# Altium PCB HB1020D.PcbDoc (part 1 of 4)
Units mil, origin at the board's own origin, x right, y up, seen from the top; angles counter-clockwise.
Board outline 4729.44 x 3075.9 mil, 2 copper layers (Top Layer, Bottom Layer); 113 components, 129 nets, 454 pads, 503 vias.
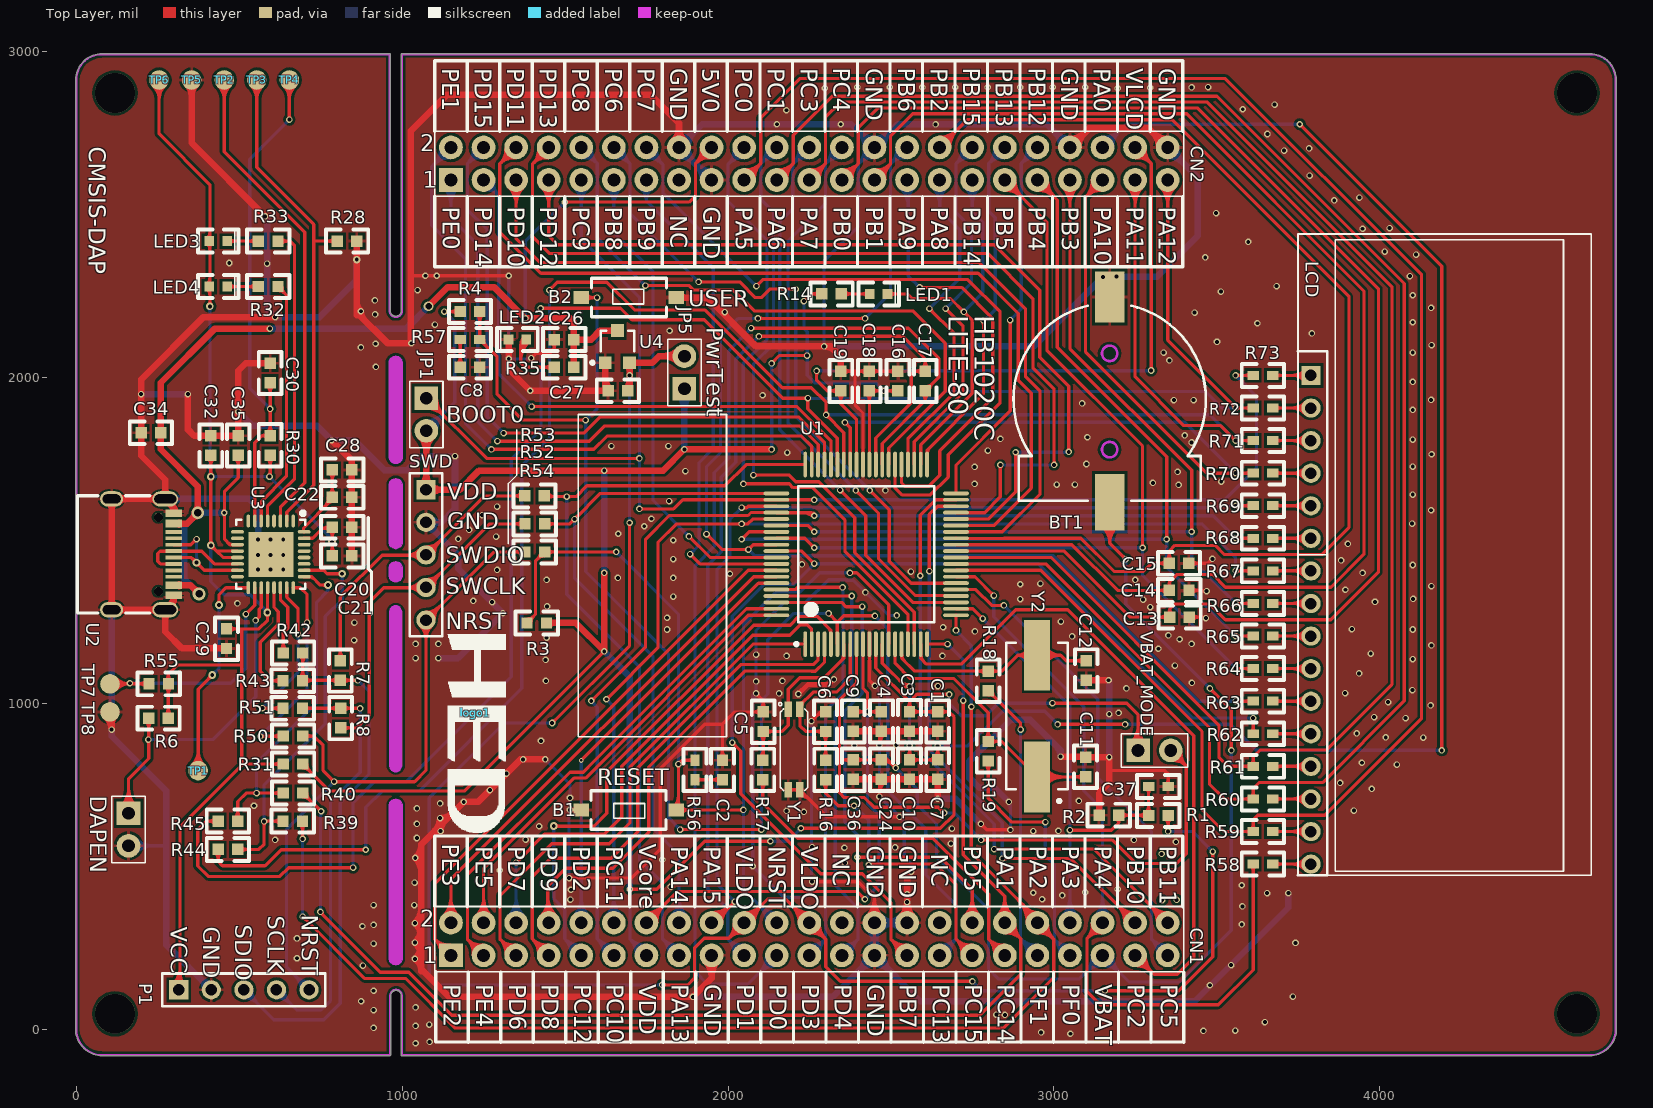
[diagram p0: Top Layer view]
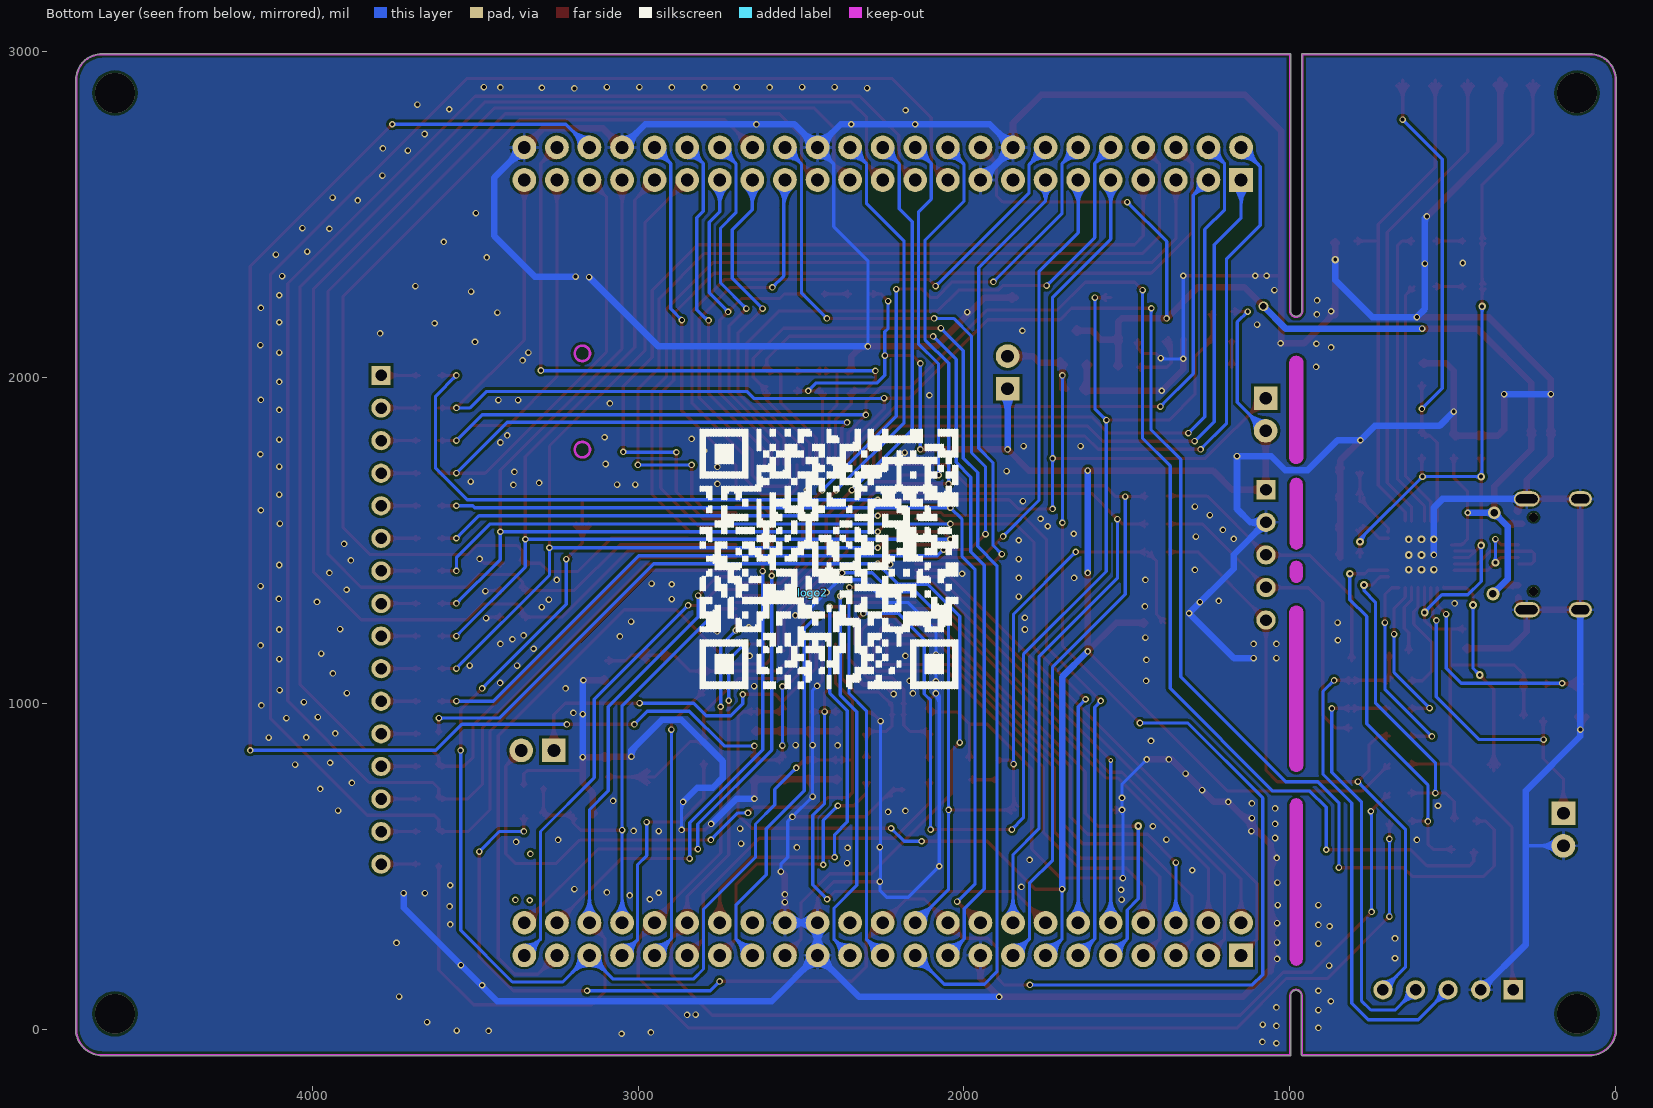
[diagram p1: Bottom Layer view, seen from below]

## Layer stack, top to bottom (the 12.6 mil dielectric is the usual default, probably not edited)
Top Layer: signal copper 1.4
Dielectric: dielectric 12.6, FR-4, Dk 4.8
Bottom Layer: signal copper 1.4

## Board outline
-2.52,0.05 ccw(c78.74,0.05) 78.74,-81.21 ccw(c78.74,-78.69) 78.81,-81.21 962,-81.21 ccw(c962,-78.69) 964.52,-78.69 964.52,103 cw(c981,103) 997.44,104.27 ccw(c999.61,103) 997.09,103 997.09,-78.69 ccw(c999.61,-78.69) 999.61,-81.21 4645.67,-81.21 ccw(c4645.67,0.05) 4726.92,0.05 ccw(c4724.41,0.05) 4726.92,0.07 4726.92,2913.43 cw(c4724.41,2913.43) 4726.92,2913.41 4726.92,2913.43 ccw(c4645.67,2913.43) 4645.73,2994.69 ccw(c4645.67,2992.17) 4645.67,2994.69 1000,2994.69 ccw(c1000,2992.17) 997.48,2992.17 997.48,2204.83 cw(c1000,2204.83) 997.48,2204.88 997.48,2204.83 cw(c980.31,2204.83) 995.99,2197.82 cw(c980.45,2206.4) 963.65,2200.68 cw(c980.31,2204.83) 963.14,2204.77 cw(c980.31,2204.83) 963.14,2204.83 963.14,2992.17 ccw(c960.63,2992.17) 960.12,2994.64 ccw(c959.61,2992.17) 959.61,2994.69 78.8,2994.69 ccw(c78.8,2992.17) 78.74,2994.69 cw(c78.8,2913.43) 78.8,2994.69 78.74,2994.69 ccw(c78.8,2913.43) -2.45,2913.99 ccw(c0,2913.43) -2.51,2913.43
cut-out: 959.99,217 959.99,687 cw(c980,687) 1000.02,687 1000.02,217 cw(c980,217)
cut-out: 959.99,1392 959.99,1416 cw(c980,1416) 1000.02,1416 1000.02,1392 cw(c980,1392)
cut-out: 959.99,1494 959.99,1671 cw(c980,1671) 1000.02,1671 1000.02,1494 cw(c980,1494)
cut-out: 959.99,810 ccw(c980,810) 1000.02,810 1000.02,1280 ccw(c980,1280) 959.99,1280
cut-out: 998.94,1756.79 998.94,2045.37 ccw(c979.25,2045.37) 959.57,2045.37 959.57,1756.79 ccw(c979.25,1756.79)

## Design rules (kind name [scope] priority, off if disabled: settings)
Clearance [(IsPad and InComponent('U1'))] p1: gap=7
Clearance Clearance_CN [(IsPad and InComponent('CN1','CN4','U2'))] p2: gap=6
Clearance Clearance_Pad [All] p3: gap=8
Clearance Clearance_poly [(InPolygon)] p4: gap=12
ComponentClearance [All] p1: gap=0 collisioncheckmode=3 verticalgap=0 showdistances=FALSE
HoleSize [All] p1: absolutevalues=TRUE maxlimit=130 minlimit=1 maxpercent=80.000 minpercent=20.000
MinimumSolderMaskSliver [All] p1: minsoldermaskwidth=0
PolygonConnect PolygonConnect_Pads [IsPad] p1: connectstyle=Relief reliefconductorwidth=10 reliefentries=4 polygonreliefangle="90 Angle"
PolygonConnect [All] p2: connectstyle=Direct reliefconductorwidth=10 reliefentries=4 polygonreliefangle="90 Angle"
RoutingVias [All] p1: holewidth=12 width=20 viastyle="Through Hole" minholewidth=10 minwidth=18 maxholewidth=300 maxwidth=500
SilkToSilkClearance [All] p1: silktosilkclearance=0
SilkscreenOverComponentPads [IsPad] p1: minsilkscreentomaskgap=0
SolderMaskExpansion [All] p1: expansion=4
TestPointUsage [All] p1: valid=0 allowmultiple=FALSE
Testpoint [All] p1: side=3 testpointundercomponent=TRUE minsize=40 maxsize=100 preferedsize=60 minholesize=0 maxholesize=40 preferedholesize=32 testpointgrid=1 style=297 order=0123456789
Width [All] p1: maxlimit=20 minlimit=8 preferedwidth=10
19 further rules are at their usual default settings.

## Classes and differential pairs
component class LINK: C20 C21 C22 C28 C29 C30 C32 C34 C35 D4 DAPEN JP6 JP9 LED3 LED4 P0 P1 R6 R7 R8 R28 R30 R31 R32 R33 R38 R39 R40 R42 R43 R44 R45 R47 R48 R49 R50 R51 R55 TP1 TP2 TP3 TP4 TP5 TP6 TP7 TP8 U2 U3
component class mcu: B1 B2 BT1 C1 C2 C3 C4 C5 C6 C7 C8 C9 C10 C11 C12 C13 C14 C15 C16 C17 C18 C19 C24 C26 C27 C36 C37 CN1 CN2 D1 JP1 JP5 LCD LED1 LED2 logo1 logo2 R1 R2 R3 R4 R14 R16 R17 R18 R19 R35 R52 R53 R54 R56 R57 R58 R59 R60 R61 R62 R63 R64 R65 R66 R67 R68 R69 R70 R71 R72 R73 SWD U1 U4 VBAT_MODE Y1 Y2

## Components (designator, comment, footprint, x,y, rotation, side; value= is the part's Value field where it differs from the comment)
B1 "TS-1101-C-W" 按键_TS-1101-C-W 1549.61,673 r0 top
B2 "TS-1101-C-W" 按键_TS-1101-C-W 1840.95,2246 r180 top
BT1 "CR1220电池座" CR1220 3171.61,1617.79 r90 top locked
C1 "4.7u" 0603#1 2643.6,914.79 r90 top
C2 "0.1u" 0603#1 1983,766 r90 top
C3 "0.1u" 0603#1 2557.27,915 r90 top
C4 "0.1u" 0603#1 2470.93,974.79 r270 top
C5 "10p" 0603#1 2108,974 r270 top
C6 "10p" 0603#1 2299.61,974 r270 top
C7 "1u" 0603#1 2643.61,766.79 r90 top
C8 "0.1u" 0603#1 1238,2032 r180 top
C9 "1u" 0603#1 2384.6,974.79 r270 top
C10 "0.1u" 0603#1 2557.27,766.79 r90 top
C11 "DNP" 0603#1 3097.61,775.31 r90 top
C12 "DNP" 0603#1 3099.61,1131.31 r270 top
C13 "0.1u" 0603#1 3356,1265 r0 top
C14 "0.1u" 0603#1 3355,1347 r0 top
C15 "0.1u" 0603#1 3354.29,1430.11 r0 top
C16 "4.7u" 0603#1 2521.61,1959.79 r90 top
C17 "0.1u" 0603#1 2605.61,1959.79 r90 top
C18 "0.1u" 0603#1 2433.61,1959.79 r90 top
C19 "0.1u" 0603#1 2346.27,2019.79 r270 top
C20 "1u" 0603#1 845.61,1540.79 r180 top
C21 "10n" 0603#1 845.61,1452.79 r180 top
C22 "4.7u" 0603#1 845.61,1632.79 r180 top
C24 "1u" 0603#1 2470.93,766.79 r90 top
C26 "10u" 0603#1 1467,2117 r0 top
C27 "10u" 0603#1 1632,1960 r0 top
C28 "0.1u" 0603#1 845.61,1716.79 r180 top
C29 "0.1u" 0603#1 460.61,1168.79 r90 top
C30 "0.1u" 0603#1 594.61,1984.31 r90 top
C32 "1u" 0603#1 412.61,1761.79 r90 top
C34 "0.1u" 0603#1 198.61,1830.79 r0 top
C35 "1u" 0603#1 496.61,1761.79 r90 top
C36 "0.1u" 0603#1 2384.6,766.79 r90 top
C37 "0.1u" 0603#2 3291,745 r0 top
CN1 "Header 23x2" HEADER_1X23_2.54 1149.61,226.79 r0 top locked
CN2 "Header 23x2" HEADER_1X23_2.54 1149.61,2606.79 r0 top
DAPEN "Header 1x2" HEADER_1X2_2.54 160,613 r270 top (schematic designator DAP_EN)
JP1 "Header 1x2" HEADER_1X2_2.54 1074,1887 r270 top
JP5 "Header 1x2" HEADER_1X2_2.54 1866,2016 r90 top
LCD "YR90724A_8COM*8SEG" LCD_YR_8COM*8SEG 3749.46,2637.84 r270 top
LED1 "LED_G" "0603 - p" 2435,2257 r0 top
LED2 "LED_R" 0603-P 1381,2117 r180 top
LED3 "LED_G" 0603-P 407.61,2419.31 r0 top
LED4 "LED_R" 0603-P 407.61,2279.79 r0 top
logo1 "logo" LOGO 1224.38,971.38 r270 top
logo2 "SIGN" SIGN 2465,1340 r90 bottom
P1 "Header 1x5" HDR1X5_2.54 314,121 r0 top
R1 "10K" 0603#1 3291,656 r0 top
R2 "10K" 0603#1 3139,657 r0 top
R3 "10K" 0603#1 1443,1247 r180 top
R4 "4.7k" 0603#1 1238,2203 r180 top
R6 "4.7K" 0603#1 222,955 r0 top
R7 "0R" 0603#1 810,1071 r90 top
R8 "0R" 0603#1 811,985 r270 top
R14 "510R" 0603#1 2348,2257 r180 top
R16 "DNP" 0603#1 2299.61,766 r90 top
R17 "DNP" 0603#1 2107,766 r90 top
R18 "0R" 0603#1 2798.61,1099.31 r270 top
R19 "0R" 0603#1 2798.61,883.31 r270 top
R28 "DNP" 0603#1 860.61,2419.31 r180 top
R30 "DNP" 0603#1 594.61,1762.31 r90 top
R31 "DNP" 0603#1 635,814 r0 top
R32 "1K" 0603#1 618.61,2279.79 r180 top
R33 "1K" 0603#1 618.61,2419.31 r180 top
R35 "1K" 0603#1 1467,2032 r0 top
R39 "0R" 0603#1 634,639 r0 top
R40 "0R" 0603#1 635,725 r0 top
R42 "150R" 0603#1 635,1155 r0 top
R43 "150R" 0603#1 634,1070 r0 top
R44 "DNP" 0603#1 495,552 r180 top
R45 "DNP" 0603#1 495,639 r180 top
R50 "150R" 0603#1 635,900 r0 top
R51 "150R" 0603#1 634,985 r0 top
R52 "470R" 0603#1 1377,1551 r0 top
R53 "470R" 0603#1 1376,1637 r0 top
R54 "470R" 0603#1 1377,1465 r0 top
R55 "4.7K" 0603#1 282.61,1060.31 r180 top
R56 "10R" 0603#2 1899,826 r270 top
R57 "10R" 0603#2 1238,2117 r180 top
R58 "0R" 0603#2 3612,507 r0 top
R59 "0R" 0603#2 3612,607 r0 top
R60 "0R" 0603#2 3612,707 r0 top
R61 "0R" 0603#2 3612,807 r0 top
R62 "0R" 0603#2 3612,907 r0 top
R63 "0R" 0603#2 3612,1007 r0 top
R64 "0R" 0603#2 3612,1107 r0 top
R65 "0R" 0603#2 3612,1207 r0 top
R66 "0R" 0603#2 3612,1307 r0 top
R67 "0R" 0603#2 3612,1407 r0 top
R68 "0R" 0603#2 3612,1507 r0 top
R69 "0R" 0603#2 3612,1607 r0 top
R70 "0R" 0603#2 3612,1707 r0 top
R71 "0R" 0603#2 3612,1807 r0 top
R72 "0R" 0603#2 3612,1907 r0 top
R73 "0R" 0603#2 3612,2007 r0 top
SWD "Header 1x5" HDR1X5_2.54 1073,1656 r270 top
TP1 "TEST_POINT" TEST_POINT 335.61,798.79 r180 top
TP2 "TEST_POINT" TEST_POINT 415.61,2918.79 r180 top locked
TP3 "TEST_POINT" TEST_POINT 515.61,2918.79 r180 top locked
TP4 "TEST_POINT" TEST_POINT 615.61,2918.79 r180 top locked
TP5 "TEST_POINT" TEST_POINT 315.61,2918.79 r180 top locked
TP6 "TEST_POINT" TEST_POINT 258.61,2951.79 r90 top locked
TP7 "TEST_POINT" TEST_POINT 108.04,1098 r90 top
TP8 "TEST_POINT" TEST_POINT 108.04,1012 r90 top
U1 "" LQFP_80N_12X12 2424.27,1457.79 r90 top locked
U2 "TYPE-C-16P" HED-KH-TYPE-C-16P 272.61,1627.79 r270 top
U3 "CIU98_H" HED-QFN-32_5x5x05P 596.61,1457.79 r180 top
U4 "ME6210A33M3G" SOT-23-3 1658,2091 r0 top
VBAT_MODE "Header 1x2" HEADER_1X2_2.54 3309,856 r0 top
Y1 "32.768KHz" XTAL-MC146 2185.27,982.79 r270 top
Y2 "DNP" XTAL_HC49/SMD 2948.61,961.31 r90 top

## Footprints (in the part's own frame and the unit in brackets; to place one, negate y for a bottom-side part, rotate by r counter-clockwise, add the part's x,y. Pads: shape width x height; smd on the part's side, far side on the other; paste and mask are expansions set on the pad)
0603#1 [mil]
  rect 35x35 smd: 1(0,0) 2(60,0)
  silkscreen extent -35,-35 95,35
0603#2 [mil]
  rect 35x27.56 smd: 1(0,0) 2(60,0)
  silkscreen extent -35,-35 95,35
"0603 - p" [mil]
  rect 30x30 smd: 1(0,0) 2(55,0)
  silkscreen extent -35,-35 90,35, body extent 1,-15 60,15, height 10
0603-P [mil]
  rect 30x30 smd: 1(0,0) 2(55,0)
  silkscreen extent -35,-35 90,35, body extent 1,-15 60,15, height 10
CR1220 [mm]
  rect 4.4x2.3 smd: 1(0,0)
  rect 4x2.3 smd: 2(16,0)
  Keep-Out Layer circle w0.203: c4.1,0 r0.6
  Keep-Out Layer circle w0.203: c11.6,0 r0.6
  silkscreen extent 0.1,-7.5 15.31,7.5
HDR1X5_2.54 [mm]
  rect 1.5x1.5 hole 0.9: 1(0,0)
  round 1.5 hole 0.9: 2(2.54,0) 3(5.08,0) 4(7.62,0) 5(10.16,0)
  silkscreen extent -1.27,-1.27 11.43,1.27
HEADER_1X2_2.54 [mm]
  rect 1.85x1.85 / inner round 1.85 / far side rect 1.85x1.85 hole 1: 1(-1.27,0)
  round 1.85 hole 1: 2(1.27,0)
  silkscreen extent -2.58,-1.3 2.58,1.3, body extent -2.67,-1.3 2.58,1.3, height 8.38
HEADER_1X23_2.54 [mm]
  rect 1.85x1.85 / inner round 1.85 / far side rect 1.85x1.85 hole 1: 1(0,0)
  round 1.85 hole 1: 2(0,2.54) 3(2.54,0) 4(2.54,2.54) 5(5.08,0) 6(5.08,2.54) 7(7.62,0) 8(7.62,2.54) 9(10.16,0) 10(10.16,2.54) 11(12.7,0) 12(12.7,2.54) 13(15.24,0) 14(15.24,2.54) 15(17.78,0) 16(17.78,2.54) 17(20.32,0) 18(20.32,2.54) 19(22.86,0) 20(22.86,2.54) 21(25.4,0) 22(25.4,2.54) 23(27.94,0) 24(27.94,2.54) 25(30.48,0) 26(30.48,2.54) 27(33.02,0) 28(33.02,2.54) 29(35.56,0) 30(35.56,2.54) 31(38.1,0) 32(38.1,2.54) 33(40.64,0) 34(40.64,2.54) 35(43.18,0) 36(43.18,2.54) 37(45.72,0) 38(45.72,2.54) 39(48.26,0) 40(48.26,2.54) 41(50.8,0) 42(50.8,2.54) 43(53.34,0) 44(53.34,2.54) 45(55.88,0) 46(55.88,2.54)
  silkscreen extent -1.27,-1.27 57.15,3.81, body extent -1.27,-1.4 57.15,3.81, height 8.38
HED-KH-TYPE-C-16P [mm]
  oval 1.2x2 hole 0.7 slot 1.7 at 90 deg: 1(0,0) 2(8.64,0)
  oval 1.2x1.8 hole 0.7 slot 1.4 at 90 deg: 3(0,-4.18) 4(8.64,-4.18)
  rect 0.3x1.3 smd: A1(0.97,0.65) A4(1.77,0.65) A5(3.07,0.65) A6(4.07,0.65) A7(4.57,0.65) A8(5.57,0.65) A9(6.87,0.65) A12(7.67,0.65) B1(7.37,0.65) B4(6.57,0.65) B5(6.07,0.65) B6(5.07,0.65) B7(3.57,0.65) B8(2.57,0.65) B9(2.07,0.65) B12(1.27,0.65)
  round 0.7 hole 0.7 unplated: ""(1.43,-0.53) ""(7.21,-0.53)
  silkscreen extent -0.25,-6.84 8.89,-1.19
HED-QFN-32_5x5x05P [mm]
  oval 0.28x1 smd: 1(-1.75,-2.6) 2(-1.25,-2.6) 3(-0.75,-2.6) 4(-0.25,-2.6) 5(0.25,-2.6) 6(0.75,-2.6) 7(1.25,-2.6) 8(1.75,-2.6) 17(1.75,2.6) 18(1.25,2.6) 19(0.75,2.6) 20(0.25,2.6) 21(-0.25,2.6) 22(-0.75,2.6) 23(-1.25,2.6) 24(-1.75,2.6)
  oval 1x0.28 smd: 9(2.6,-1.75) 10(2.6,-1.25) 11(2.6,-0.75) 12(2.6,-0.25) 13(2.6,0.25) 14(2.6,0.75) 15(2.6,1.25) 16(2.6,1.75) 25(-2.6,1.75) 26(-2.6,1.25) 27(-2.6,0.75) 28(-2.6,0.25) 29(-2.6,-0.25) 30(-2.6,-0.75) 31(-2.6,-1.25) 32(-2.6,-1.75)
  rect 3.5x3.5 smd: 33(0,0)
  silkscreen extent -2.7,-3.35 2.7,2.7
LCD_YR_8COM*8SEG [mm] "5V 8COM*8SEG"
  rect 1.5x1.5 hole 0.9: 1(16.03,1.016)
  round 1.5 hole 0.9: 2(18.57,1.016) 3(21.11,1.016) 4(23.65,1.016) 5(26.19,1.016) 6(28.73,1.016) 7(31.27,1.016) 8(33.81,1.016) 9(36.35,1.016) 10(38.89,1.016) 11(41.43,1.016) 12(43.97,1.016) 13(46.51,1.016) 14(49.05,1.016) 15(51.59,1.016) 16(54.13,1.016)
  silkscreen extent 5,0 55,22.86
LOGO [mil]
  silkscreen extent -241,-83 369,93
LQFP_80N_12X12 [mm]
  oval 2x0.3 smd: 1(-7,4.75) 2(-7,4.25) 3(-7,3.75) 4(-7,3.25) 5(-7,2.75) 6(-7,2.25) 7(-7,1.75) 8(-7,1.25) 9(-7,0.75) 10(-7,0.25) 11(-7,-0.25) 12(-7,-0.75) 13(-7,-1.25) 14(-7,-1.75) 15(-7,-2.25) 16(-7,-2.75) 17(-7,-3.25) 18(-7,-3.75) 19(-7,-4.25) 20(-7,-4.75) 41(7,-4.75) 42(7,-4.25) 43(7,-3.75) 44(7,-3.25) 45(7,-2.75) 46(7,-2.25) 47(7,-1.75) 48(7,-1.25) 49(7,-0.75) 50(7,-0.25) 51(7,0.25) 52(7,0.75) 53(7,1.25) 54(7,1.75) 55(7,2.25) 56(7,2.75) 57(7,3.25) 58(7,3.75) 59(7,4.25) 60(7,4.75)
  oval 0.3x2 smd: 21(-4.75,-7) 22(-4.25,-7) 23(-3.75,-7) 24(-3.25,-7) 25(-2.75,-7) 26(-2.25,-7) 27(-1.75,-7) 28(-1.25,-7) 29(-0.75,-7) 30(-0.25,-7) 31(0.25,-7) 32(0.75,-7) 33(1.25,-7) 34(1.75,-7) 35(2.25,-7) 36(2.75,-7) 37(3.25,-7) 38(3.75,-7) 39(4.25,-7) 40(4.75,-7) 61(4.75,7) 62(4.25,7) 63(3.75,7) 64(3.25,7) 65(2.75,7) 66(2.25,7) 67(1.75,7) 68(1.25,7) 69(0.75,7) 70(0.25,7) 71(-0.25,7) 72(-0.75,7) 73(-1.25,7) 74(-1.75,7) 75(-2.25,7) 76(-2.75,7) 77(-3.25,7) 78(-3.75,7) 79(-4.25,7) 80(-4.75,7)
  silkscreen extent -7.12,-5.3 5.3,5.57, body extent -6,-6 6,6, height 1.4
SIGN [mil]
  silkscreen extent -294,-446 501,344
SOT-23-3 [mm]
  rect 1x1 smd: 1(-0.889,-1.143) 2(1.011,-1.143) 3(0.061,1.357)
  silkscreen extent -2.01,-1.27 1.36,1.36, body extent -1.39,-1.29 1.51,1.51, height 1.2
TEST_POINT [mil]
  round 60 smd: 1(-38,5)
XTAL-MC146 [mm]
  rect 1.2x0.6 smd mask+0.05: 1(0,0) 2(6.3,0) 3(6.3,0.9) 4(0,0.9)
  silkscreen extent -0.51,-0.76 6.35,1.52
XTAL_HC49/SMD [mm]
  rect 5.5x2 smd: 1(-4.75,0) 2(4.75,0)
  silkscreen extent -6.75,-2.4 5.7,2.4, body extent -6.7,-2.46 6.7,2.44, height 4
按键_TS-1101-C-W [mm] "星坤品牌"
  rect 1.2x1 smd mask+0.05: 1(0,0) 2(7.4,0)
  silkscreen extent 0.76,-1.5 6.6,1.5

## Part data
B1 B2: library part SW-PB, "Switch"
BT1: library part Battery, "Multicell Battery"
C1 C11 C12 C13 C14 C15 C16 C17 C19 C36 C37: library part MCD-00009, "Capacitor, MLCC, 4.7uF, 16V, X5R, 10%, 0603, T=0.8mm"
C2: library part Capacitor, "Capacitor, MLCC, 100nF, 16V, X7R, 10%, 0603, T=0,8mm"
C3 C4 C7 C9 C10 C18 C20 C21 C28 C29 C30 C32 C35: library part MCD-00211, "Capacitor, MLCC, 100nF, 16V, X7R, 10%, 0603, T=0,8mm"
C5 C6: library part Capacitor, "Capacitor,5.6pF,0.1pF,16V,NPO,0603"
C8: library part MCD-00211, "贴片电容"
C22 C34: library part "0603 100nF 10% 50V", "贴片电容"
C24 C26 C27: library part MCD-00014, "Capacitor, MLCC, 10uF, 25V, X5R, 10%, 0805, T=0,85mm"
CN1 CN2: "Header, 19x2, 2,54mm, VR, TH, Height 5.84mm/10.16mm"
DAPEN VBAT_MODE: library part MCD-00683, "Header, 2x1, 2,54mm, VR, TH, Height 5.84mm/2.54mm - Shunt Fitted by default"
JP1 JP5: library part "Jumper_Header 2x1 Fitted", "Header, 2x1, 2,54mm, VR, TH, Height 5.84mm/2.54mm - Shunt Fitted by default"
LCD: library part LCD8COM*8SEG, "Common Anode Seven-Segment Display, Right Hand Decimal"
LED1 LED2 LED3 LED4: library part LED1, "Typical RED GaAs LED"
P1 SWD: library part SWD
R1 R2 R3 R4 R7 R8 R14 R16 R17 R18 R19 R30 R31 R32 R33 R35 R39 R40 R44 R45 R56 R57 R58 R59 R60 R61 R62 R63 R64 R65 R66 R67 R68 R69 R70 R71 R72 R73: library part Res2, "贴片电阻"
R6 R28 R42 R43 R50 R51 R52 R53 R54 R55: library part Res, "贴片电阻"
U1: library part CIU32L071Mx-LQFP80, "CIU32L071Mx"
U2: library part KH-TYPE-C-16P, "TYPE-C USB接口"
U3: library part CIU98-H
U4: library part ME6210, "贴片LDO3.3V"
Y1: library part MC146
Y2: library part XTAL_32K_NX3215SA, "Crystal 32.768kHz, 6pF, -+20PPM, R=50K, SMD"

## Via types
v1: diameter 20, hole 12, Top Layer to Bottom Layer, tented both sides, 475 vias
v2: diameter 23.62, hole 11.81, Top Layer to Bottom Layer, tented both sides, 20 vias
v3: diameter 122.05, hole 122.05, Top Layer to Bottom Layer, tented both sides, 4 vias
v4: diameter 39.37, hole 23.62, Top Layer to Bottom Layer, tented both sides, 2 vias
v5: diameter 30, hole 20, Top Layer to Bottom Layer, tented both sides, 1 vias
v6: diameter 15, hole 8, Top Layer to Bottom Layer, tented both sides, 1 vias

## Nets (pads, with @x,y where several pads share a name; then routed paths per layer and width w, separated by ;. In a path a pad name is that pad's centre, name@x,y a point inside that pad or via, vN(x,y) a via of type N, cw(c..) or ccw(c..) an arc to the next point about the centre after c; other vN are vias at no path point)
CMS_STATE: TP1.1 U3.17 | length 922.9
  Top Layer w10: TP1.1@355.93,811.47 ccw(c313.25,854.14) 373.61,854.14 ccw(c433.96,854.14) TP1.1@391.28,811.47 ; TP1.1@363,804.39 ccw(c337.39,830) 373.61,830 ccw(c409.82,830) TP1.1@384.21,804.39 ; TP1.1@373.61,793.79 373.61,1043.88 v2(416.88,1087.15) ; v2@410.07,1087.15 cw(c393.63,1087.15) 405.25,1075.53 cw(c416.88,1063.9) v2@416.88,1080.34 ; v2@432.79,1307.12 ccw(c421.16,1318.75) 437.61,1318.75 ccw(c454.05,1318.75) v2@442.42,1307.12 ; v2(437.61,1302.31) 437.61,1334.31 458.72,1355.43 U3.17@527.71,1355.43 U3.17@527.71,1357.39
  Bottom Layer w10: v2(416.88,1087.15) 437.61,1107.88 v2(437.61,1302.31) ; v2@416.88,1093.96 ccw(c416.88,1110.41) 428.51,1098.78 ccw(c440.13,1087.15) v2@423.69,1087.15 ; v2@432.79,1297.49 cw(c421.16,1285.86) 437.61,1285.86 cw(c454.05,1285.86) v2@442.42,1297.49
GND: B1.1 B2.1 BT1.2 C1.1 C2.2 C3.1 C4.2 C5.1 C6.1 C7.1 C8.1 C9.2 C10.1 C11.2 C12.2 C13.2 C14.2 C15.2 C16.2 C18.2 C19.1 C20.1 C21.1 C22.1 C24.1 C26.1 C27.1 C28.1 C29.1 C30.2 C32.2 C34.1 C35.2 C36.1 C37.2 CN1.17 CN1.27 CN1.28 CN1.30 CN2.16 CN2.17 CN2.28 CN2.40 CN2.46 DAPEN.2 LED2.2 P1.2 R2.1 R28.1 SWD.2 TP5.1 TP8.1 U1.11 U1.51 U2.1 U2.2 U2.3 U2.4 U2.A1 U2.A12 U2.B1 U2.B12 U3.33 U4.1 Y1.2 Y1.3 | length 35746.7
  Top Layer w10: 1026.61,2313 v1(1327,2313) ; v1@1067.46,2309.46 ccw(c1058.93,2300.93) 1058.93,2313 ccw(c1058.93,2325.07) v1@1067.46,2316.54 ; v1@1074.54,2309.46 cw(c1083.07,2300.93) 1083.07,2313 cw(c1083.07,2325.07) v1@1074.54,2316.54 ; v1@1102.46,2309.46 ccw(c1093.93,2300.93) 1093.93,2313 ccw(c1093.93,2325.07) v1@1102.46,2316.54 ; v1@1109.54,2309.46 cw(c1118.07,2300.93) 1118.07,2313 cw(c1118.07,2325.07) v1@1109.54,2316.54 ; v1@1323.46,2309.46 ccw(c1314.93,2300.93) 1314.93,2313 ccw(c1314.93,2325.07) v1@1323.46,2316.54 ; v1(1396,2060) 1410,2074 1451,2074 1467,2090 ; v1@1396,2065 ccw(c1396,2077.07) 1404.54,2068.54 ccw(c1413.07,2060) v1@1401,2060 ; C26.1@1458.91,2107.47 cw(c1444.1,2090) 1467,2090 ; C26.1@1467,2117 1467,2090 ; C26.1@1475.09,2107.47 ccw(c1489.9,2090) 1467,2090 ; v1(1512,464) 1703,464 1792,553 1792,799 1929,936 1983,936 ; v1@1515.54,460.46 cw(c1524.07,451.93) 1524.07,464 cw(c1524.07,476.07) v1@1515.54,467.54 ; v1@1518.54,669.46 cw(c1527.07,660.93) 1527.07,673 cw(c1527.07,685.07) v1@1518.54,676.54 ; B1.1@1534.23,663.79 ccw(c1515,648.32) v1(1515,673) ; B1.1@1534.23,682.21 cw(c1515,697.68) v1(1515,673) ; B1.1@1549.61,673 v1(1515,673) ; C2.2@1974.16,834.84 ccw(c1952.82,856.18) 1983,856.18 ccw(c2013.18,856.18) C2.2@1991.84,834.84 ; C2.2@1983,826 1983,936 ; v1@2086,1026 cw(c2086,1013.93) 2094.54,1022.46 cw(c2103.07,1031) v1@2091,1031 ; v1(2086,1031) 2108,1009 C5.1@2108,974 2021,974 1983,936 ; C5.1@2099.16,965.16 ccw(c2077.83,943.83) 2077.83,974 ccw(c2077.82,1004.18) 2099.16,982.84 ccw(c2077.82,1004.18) 2108,1004.18 ccw(c2138.18,1004.18) C5.1@2116.84,982.84 ; Y1.2@2185.27,734.76 Y1.3@2220.7,734.76 2303.6,651.86 v1(2526.96,651.86) ; Y1.2@2190.08,729.94 cw(c2201.71,718.31) 2201.71,734.76 cw(c2201.71,751.2) Y1.2@2190.08,739.57 ; Y1.3@2215.88,729.94 ccw(c2204.26,718.31) 2204.26,734.76 ccw(c2204.26,751.2) Y1.3@2215.88,739.57 ; Y1.3@2220.7,716.13 cw(c2220.7,671.18) 2252.49,702.97 ; Y1.3@2220.7,726.13 cw(c2220.7,705.32) 2235.42,720.04 ; v1(2256,946) 2284,974 C6.1@2299.61,974 ; v1@2256,951 ccw(c2256,963.07) 2264.54,954.54 ccw(c2273.07,946) v1@2261,946 ; v1(2258,453) 2400,453 2449.61,403.39 CN1.28@2449.61,326.79 ; v1@2261.54,449.46 cw(c2270.07,440.93) 2270.07,453 cw(c2270.07,465.07) v1@2261.54,456.54 ; 2268.7,958.7 cw(c2299.61,927.79) C6.1@2299.61,971.5 ; C19.1@2346.27,2019.79 2390,2019.79 ; C19.1@2355.11,2010.95 cw(c2376.44,1989.61) 2376.44,2019.79 cw(c2376.44,2049.97) C19.1@2355.11,2028.63 ; U1.51@2414.42,1733.38 2414.42,1891.57 2390,1916 2390,2019.79 ; C18.2@2424.77,2010.95 ccw(c2403.43,1989.61) 2403.43,2019.79 ccw(c2403.43,2049.97) C18.2@2424.77,2028.63 ; CN1.28@2427.39,349 ccw(c2373.76,402.64) 2449.61,402.64 ccw(c2525.45,402.64) CN1.28@2471.82,349 ; U1.11@2434.11,1182.2 2434.11,1070.89 v1(2451,1054) ; CN1.28@2434.46,341.93 ccw(c2397.9,378.49) 2449.61,378.49 ccw(c2501.31,378.49) CN1.28@2464.75,341.93 ; C18.2@2442.45,2010.95 cw(c2463.78,1989.61) 2463.78,2019.79 cw(c2463.78,2049.97) C18.2@2442.45,2028.63 ; v1@2446,1054 ccw(c2433.93,1054) 2442.46,1062.54 ccw(c2451,1071.07) v1@2451,1059 ; v1@2461.46,717.36 ccw(c2452.93,725.89) 2465,725.89 ccw(c2477.07,725.89) v1@2468.54,717.36 ; v1@2461.46,875.54 ccw(c2452.93,884.07) 2465,884.07 ccw(c2477.07,884.07) v1@2468.54,875.54 ; v1(2465,713.82) C24.1@2465,760.85 ; v1@2465,722.28 cw(c2515.44,722.28) C24.1@2479.77,757.95 ; 2465,746.42 cw(c2491.3,746.42) C24.1@2472.7,765.02 ; v1@2465,871.59 cw(c2512.33,871.59) C4.2@2479.58,905.76 ; v1(2465,872) C4.2@2465,908.85 ; 2465,895.02 cw(c2489.87,895.02) C4.2@2472.66,912.98 ; C16.2@2512.77,2010.95 ccw(c2491.43,1989.61) 2491.43,2019.79 ccw(c2491.43,2049.97) C16.2@2512.77,2028.63 ; C16.2@2521.61,2019.79 C18.2@2433.61,2019.79 2390,2019.79 ; v1@2523.43,648.32 ccw(c2514.89,639.79) 2514.89,651.86 ccw(c2514.89,663.93) v1@2523.43,655.4 ; v1@2776,625 cw(c2776,612.93) 2784.54,621.46 cw(c2793.07,630) v1@2781,630 ; v1(2776,630) 2794,612 v1(2867,612) ; v1@2863.46,608.46 ccw(c2854.93,599.93) 2854.93,612 ccw(c2854.93,624.07) v1@2863.46,615.54 ; 3170.31,794 3340.98,794 3351,783.98 C37.2@3351,745 ; C37.2@3344.79,751.21 ccw(c3329.8,766.2) 3351,766.2 ccw(c3372.2,766.2) C37.2@3357.21,751.21 ; C15.2@3414.29,1430.11 3473.11,1430.11 v1(3487,1444) ; C14.2@3415,1347 v1@3467,1347 ; C13.2@3416,1265 v1@3464,1265 ; C15.2@3423.13,1421.27 cw(c3444.46,1399.93) 3444.46,1430.11 cw(c3444.46,1460.28) C15.2@3423.13,1438.94 ; C14.2@3423.84,1338.16 cw(c3445.18,1316.82) 3445.18,1347 cw(c3445.18,1377.18) C14.2@3423.84,1355.84 ; C13.2@3424.84,1256.16 cw(c3446.18,1234.82) 3446.18,1265 cw(c3446.18,1295.18) C13.2@3424.84,1273.84 ; 3447.69,1265 cw(c3447.69,1242.69) v1@3463.46,1258.46 ; 3452.1,1347 cw(c3452.1,1328.1) v1@3465.46,1341.46 ; v1@3482,1444 cw(c3469.93,1444) 3478.46,1435.46 cw(c3487,1426.93) v1@3487,1439
  Top Layer w15: v1(2216,1029) 2245,1058 2309,1058 v1(2325,1074)
  Top Layer w20: TP8.1@90.05,958.79 cw(c56.73,919.77) v1@108.04,919.77 ; U2.4@98.41,1297.26 ccw(c75.15,1320.52) 108.04,1320.52 ccw(c140.93,1320.52) U2.4@117.67,1297.26 ; U2.3@98.41,1618.16 cw(c75.15,1594.9) 108.04,1594.9 cw(c140.93,1594.9) U2.3@117.67,1618.16 ; v1(108.04,920) TP8.1@108.04,969 ; 108.04,937.79 cw(c139.25,937.79) TP8.1@117.18,959.86 ; U2.4@129.48,1278 cw(c152.74,1254.75) 152.74,1287.63 cw(c152.74,1320.52) U2.4@129.48,1297.26 ; U2.3@129.48,1618.16 cw(c152.74,1594.9) 152.74,1627.79 cw(c152.74,1660.67) U2.3@129.48,1637.42 ; C34.1@193.3,1825.48 cw(c180.5,1812.68) 198.61,1812.68 cw(c216.71,1812.68) C34.1@203.91,1825.48 ; C34.1@193.3,1836.09 ccw(c180.5,1848.89) 198.61,1848.89 ccw(c216.71,1848.89) C34.1@203.91,1836.09 ; U2.2@247.23,1278 ccw(c223.97,1254.75) 223.97,1287.63 ccw(c223.97,1320.52) U2.2@247.23,1297.26 ; U2.1@247.23,1618.16 ccw(c223.97,1594.9) 223.97,1627.79 ccw(c223.97,1660.67) U2.1@247.23,1637.42 ; U2.2@262.97,1278 cw(c239.72,1254.75) 272.61,1254.75 cw(c305.49,1254.75) U2.2@282.24,1278 ; U2.1@262.97,1637.42 ccw(c239.72,1660.67) 272.61,1660.67 ccw(c305.49,1660.67) U2.1@282.24,1637.42 ; U2.1@281.86,1615.81 cw(c266.96,1588.35) U2.A1@298.2,1588.35 ; U2.2@282.2,1299.79 ccw(c269.03,1325.82) U2.A12@298.2,1325.82 298.2,1313.23 U2.2@272.61,1287.63 ; 296.83,1603.56 cw(c282.87,1589.6) U2.A1@302.61,1589.6 ; U2.A1@298.2,1589.6 298.2,1602.19 U2.1@272.61,1627.79 ; TP5.1@339.46,2899.65 cw(c305.32,2865.5) 353.61,2865.5 cw(c401.89,2865.5) TP5.1@367.75,2899.65 ; v1(342.39,1949.39) 342.39,1840.61 361.21,1821.79 C32.2@412.61,1821.79 C35.2@496.61,1821.79 v1(496.61,1896) 496.61,2021.31 519.61,2044.31 C30.2@594.61,2044.31 ; TP5.1@353.61,2913.79 353.61,2720.39 v1(579,2495) ; C32.2@407.3,1816.48 ccw(c394.5,1803.68) 394.5,1821.79 ccw(c394.5,1839.89) C32.2@407.3,1827.09 ; C32.2@417.91,1816.48 cw(c430.71,1803.68) 430.71,1821.79 cw(c430.71,1839.89) C32.2@417.91,1827.09 ; C29.1@455.3,1163.48 ccw(c442.5,1150.68) 442.5,1168.79 ccw(c442.5,1186.89) C29.1@455.3,1174.09 ; C29.1@460.61,1168.79 324.12,1168.79 272.61,1220.31 U2.2@272.61,1287.63 ; C35.2@491.3,1816.48 ccw(c478.5,1803.68) 478.5,1821.79 ccw(c478.5,1839.89) 491.3,1827.09 ccw(c478.5,1839.89) 496.61,1839.89 ccw(c514.71,1839.89) C35.2@501.91,1827.09 ; C30.2@589.3,2039 ccw(c576.5,2026.2) 576.5,2044.31 ccw(c576.5,2062.41) C30.2@589.3,2049.61 ; v1(610,2186) 390,2186 198.61,1994.61 v1(198.61,1949.39) C34.1@198.61,1830.79 198.61,1760.31 272.61,1686.31 U2.1@272.61,1627.79 ; v1(783,1808) 845.61,1745.39 C28.1@845.61,1716.79 ; C28.1@840.3,1722.09 ccw(c827.5,1734.89) 845.61,1734.89 ccw(c863.71,1734.9) C28.1@850.91,1722.09 ; C20.1@844.61,1537.79 844.61,1447.79 844.61,1632.79 C28.1@844.61,1711.79 ; 844.61,1561.31 ccw(c866.13,1561.31) C20.1@850.91,1546.09 ; 844.61,1612.27 cw(c866.13,1612.27) C22.1@850.91,1627.48 ; 844.61,1653.31 ccw(c866.13,1653.31) C22.1@850.91,1638.09 ; 844.61,1696.27 cw(c866.13,1696.27) C28.1@850.91,1711.49 ; R28.1@855.3,2414 cw(c842.5,2401.2) 860.61,2401.2 cw(c878.71,2401.2) R28.1@865.91,2414 ; 860.61,2191.09 cw(c873.52,2191.09) v1(873,2204) ; 860.61,2233.92 ccw(c902.92,2233.92) v1(873,2204) ; R28.1@860.61,2419.31 v2(860.61,2362.39) 860.61,2200.39 956,2105 v1@1023,2105 ; 884.31,2176.69 cw(c911.63,2204) v1(873,2204) ; v1(1027.87,2105.67) 1027.87,2105 v1@1023,2105 ; 1059,178.27 ccw(c1013.4,178.27) v1(1039,216) ccw(c990.72,264.28) 1059,264.28 ; 1059,217.72 ccw(c990.72,217.72) v1(1039,266) ccw(c990.72,314.28) 1059,314.28 ; 1059,277.72 ccw(c990.72,277.72) v1(1039,326) ccw(c990.72,374.28) 1059,374.28 ; 1059,480.13 ccw(c994.13,480.13) v1(1040,526) ccw(c1003.08,568) 1059,568 ; 1085.56,594.56 cw(c1118,562.13) v1(1118,608) cw(c1163.87,608) 1131.44,640.44 ; 1099.74,608.74 ccw(c1060.47,648) v1(1116,648) ccw(c1116,703.53) 1155.26,664.26 ; LED2.2@1326,2117 1327,2116 v1(1327,2058) 1327,2026 v1(1393,1960) C27.1@1632,1960 1623,1969 U4.1@1623,2046 ; 1357.34,822.34 cw(c1371,808.69) v1(1371,828) ; v1(1439,828) 1363,828 1232.89,697.89 v1(1188.89,697.89) 1059,568 ; U4.1@1616.15,2039.15 cw(c1599.62,2022.62) 1623,2022.62 cw(c1646.38,2022.62) U4.1@1629.85,2039.15 ; 1623,1999.83 ccw(c1671.83,1999.83) C27.1@1637.3,1965.3 ; C27.1@1626.7,1954.7 ccw(c1613.89,1941.89) 1613.89,1960 ccw(c1613.89,1978.11) C27.1@1626.7,1965.3 ; CN2.16@1830.93,2725.47 ccw(c1785.83,2770.57) 1849.61,2770.57 ccw(c1913.38,2770.57) CN2.16@1868.29,2725.47 ; B2.1@1840.95,2246 1936,2246 2086,2096 v1(2295,2096) ; CN2.16@1849.61,2706.79 1849.61,2781.39 1763,2868 1136.82,2868 1026.61,2757.79 1026.61,2313 1026.61,2108.61 v1@1023,2105 ; B2.1@1851.73,2239.15 cw(c1868.26,2222.62) 1868.26,2246 cw(c1868.26,2269.38) B2.1@1851.73,2252.85 ; CN1.17@1930.93,208.11 cw(c1885.83,163.01) 1949.61,163.01 cw(c2013.38,163.01) CN1.17@1968.29,208.11 ; CN1.17@1949.61,226.79 1949.61,156.61 v1(1892,99) 1144,99 1059,184 1059,568 ; 1974.64,2207.36 ccw(c1990,2222.73) v1(1990,2201) ccw(c2011.73,2201) 1996.36,2185.64 ; 2325,2086 ccw(c2300,2061) v1(2295,2096) ; 2329.14,2081.86 ccw(c2295,2047.72) v1(2295,2096) ; C19.1@2340.96,2025.09 ccw(c2328.16,2037.89) 2346.27,2037.89 ccw(c2364.37,2037.89) C19.1@2351.57,2025.09 ; C19.1@2346.27,2019.79 2346.27,2064.73 2315,2096 v1(2295,2096) ; C36.1@2384.6,766.79 C24.1@2470.93,766.79 C10.1@2557.27,766.79 C7.1@2643.61,766.79 v1(2643.61,707.61) ; C9.2@2384.6,914.79 C4.2@2470.93,914.79 2557.27,914.79 C1.1@2643.6,914.79 ; C36.1@2389.9,761.48 cw(c2402.71,748.68) 2402.71,766.79 cw(c2402.71,784.89) C36.1@2389.9,772.09 ; C9.2@2389.9,909.48 cw(c2402.71,896.68) 2402.71,914.79 cw(c2402.71,932.89) C9.2@2389.9,920.09 ; C24.1@2465.63,761.48 ccw(c2452.83,748.68) 2452.83,766.79 ccw(c2452.83,784.89) C24.1@2465.63,772.09 ; C4.2@2465.63,909.48 ccw(c2452.83,896.68) 2452.83,914.79 ccw(c2452.83,932.89) C4.2@2465.63,920.09 ; C24.1@2476.24,761.48 cw(c2489.04,748.68) 2489.04,766.79 cw(c2489.04,784.89) C24.1@2476.24,772.09 ; C4.2@2476.24,909.48 cw(c2489.04,896.68) 2489.04,914.79 cw(c2489.04,932.89) C4.2@2476.24,920.09 ; CN1.30@2530.93,345.47 ccw(c2485.83,390.57) 2549.61,390.57 ccw(c2613.38,390.57) CN1.30@2568.29,345.47 ; 2538.66,914.79 ccw(c2538.66,933.61) C3.1@2551.97,920.3 ; 2539.67,914.79 cw(c2539.67,897.4) C3.1@2551.97,909.7 ; CN1.30@2549.61,326.79 2549.61,471.61 v1(2562,484) ; 2549.61,454.08 cw(c2591.92,454.08) v1(2562,484) ; 2549.61,466.47 cw(c2568.2,466.47) v1(2562,484) ; C10.1@2551.97,761.48 ccw(c2539.16,748.68) 2539.16,766.79 ccw(c2539.17,784.89) C10.1@2551.97,772.09 ; C10.1@2562.57,761.48 cw(c2575.38,748.68) 2575.38,766.79 cw(c2575.37,784.89) C10.1@2562.57,772.09 ; C3.1@2562.57,909.7 cw(c2574.87,897.4) 2574.87,914.79 ; C3.1@2562.57,920.3 ccw(c2575.89,933.61) 2575.89,914.79 ; C7.1@2638.3,772.09 cw(c2625.5,784.89) 2625.5,766.79 cw(c2625.5,748.68) 2638.3,761.48 cw(c2625.5,748.68) 2643.61,748.68 ; C1.1@2638.3,909.48 ccw(c2625.49,896.68) 2625.49,914.79 ccw(c2625.5,932.89) C1.1@2638.3,920.09 ; 2643.61,748.67 cw(c2661.72,748.67) C7.1@2648.91,761.48 ; v1(3021,837) C11.2@3095.91,837 ; CN2.40@3049.61,2706.79 3107.87,2765.06 3291.34,2765.06 CN2.46@3349.61,2706.79 ; CN2.40@3049.61,2733.21 ccw(c3049.61,2796.98) 3094.7,2751.89 ccw(c3139.8,2706.79) CN2.40@3076.02,2706.79 ; 3075.41,837 cw(c3075.41,813.11) C11.2@3092.3,830 ; C11.2@3097.61,835.31 v1(3170.31,835.31) 3170.31,794 3170.31,756.31 3139,725 R2.1@3139,657 ; C12.2@3099.61,1071.31 v1(3168.31,1071.31) ; C11.2@3102.91,830 cw(c3115.71,817.2) 3115.71,835.31 cw(c3115.71,853.41) C11.2@3102.91,840.61 ; C12.2@3104.91,1066 cw(c3117.71,1053.2) 3117.71,1071.31 cw(c3117.71,1089.41) C12.2@3104.91,1076.61 ; R2.1@3133.7,662.3 ccw(c3120.89,675.11) 3139,675.11 ccw(c3157.11,675.11) R2.1@3144.3,662.3 ; CN2.46@3323.19,2706.79 ccw(c3259.41,2706.79) 3304.51,2751.89 ccw(c3349.61,2796.98) CN2.46@3349.61,2733.21 ; U2.2@272.61,1287.63 U2.4@108.04,1287.63 U2.3@108.04,1627.79 U2.1@272.61,1627.79 ; 844.61,1473.31 ccw(c866.13,1473.31) 850.91,1458.09 cw(c866.13,1473.31) 844.61,1473.31 ; 844.61,1520.27 cw(c866.13,1520.27) 850.91,1535.48 ccw(c866.13,1520.27) 844.61,1520.27
  Bottom Layer w10: DAPEN.2@160,563 271,563 ; DAPEN.2@175.14,547.86 cw(c211.71,511.29) 211.71,563 cw(c211.71,614.71) DAPEN.2@175.14,578.14 ; DAPEN.2@182.22,540.79 cw(c235.85,487.15) 235.85,563 cw(c235.85,638.85) DAPEN.2@182.22,585.22 ; v1@1323.46,2061.54 ccw(c1314.93,2070.07) 1327,2070.07 ccw(c1339.07,2070.07) 1330.54,2061.54 ccw(c1341.51,2072.51) 1341.51,2056.99 ; v1@1323.46,2309.46 cw(c1314.93,2300.93) 1327,2300.93 cw(c1339.07,2300.93) v1@1330.54,2309.46 ; v1(1327,2313) v1(1327,2058) v1@1328,2059 ; v1@1328,2056.99 v1@1392.99,2056.99 ; 1376.67,2056.99 ccw(c1376.67,2079.33) v1@1392.46,2063.54 ; v1@1439,823 cw(c1439,810.93) 1447.54,819.46 cw(c1456.07,828) v1@1444,828 ; v1(1439,828) 1515,752 v1(1515,673) 1512,670 v1(1512,464) ; v1@1508.46,467.54 ccw(c1499.93,476.07) 1512,476.07 ccw(c1524.07,476.07) v1@1515.54,467.54 ; v1@1511.46,676.54 ccw(c1502.93,685.07) 1515,685.07 ccw(c1527.07,685.07) v1@1518.54,676.54 ; v1@1511.46,706.46 cw(c1502.93,697.93) 1515,697.93 cw(c1527.07,697.93) v1@1518.54,706.46 ; v1@1511.46,713.54 ccw(c1502.93,722.07) 1515,722.07 ccw(c1527.07,722.07) v1@1518.54,713.54 ; 1512,653.69 cw(c1534.31,653.69) v1@1518.54,669.46 ; v1@2072.46,503.93 ccw(c2063.93,512.47) 2076,512.47 ccw(c2088.07,512.47) v1@2079.54,503.93 ; v1@2076,495.39 cw(c2076,483.32) 2084.54,491.86 cw(c2093.07,500.39) v1@2081,500.39 ; 2076,994.79 cw(c2122.21,994.79) v1@2089.54,1027.46 ; 2076,1018.93 cw(c2098.07,1018.93) 2082.46,1034.54 ccw(c2073.93,1043.07) 2086,1043.07 ccw(c2098.07,1043.07) v1@2089.54,1034.54 ; v1@2082.46,1064.46 cw(c2073.93,1055.93) 2086,1055.93 cw(c2098.07,1055.93) v1@2089.54,1064.46 ; v1@2082.46,1071.54 ccw(c2073.93,1080.07) 2086,1080.07 ccw(c2098.07,1080.07) v1@2089.54,1071.54 ; v1@2082.46,1146.46 cw(c2073.93,1137.93) 2086,1137.93 cw(c2098.07,1137.93) v1@2089.54,1146.46 ; v1@2082.46,1153.54 ccw(c2073.93,1162.07) 2086,1162.07 ccw(c2098.07,1162.07) v1@2089.54,1153.54 ; v1@2252.46,942.46 cw(c2243.93,933.93) 2256,933.93 cw(c2268.07,933.93) v1@2259.54,942.46 ; v1@2254.46,449.46 cw(c2245.93,440.93) 2258,440.93 cw(c2270.07,440.93) v1@2261.54,449.46 ; 2256,469.9 ccw(c2274.9,469.9) v1@2261.54,456.54 ; 2256,542.1 cw(c2274.9,542.1) v1@2261.54,555.46 ; 2256,575.9 ccw(c2274.9,575.9) v1@2261.54,562.54 ; v1(2256,946) 2256,455 v1(2258,453) 2258,426 2237,405 2171.39,405 v1(2076,500.39) 2076,1021 v1(2086,1031) 2086,1224 2172.15,1310.15 2239.15,1310.15 2309,1380 2362.47,1380 2364.47,1378 2385,1378 v1(2422,1341) 2493,1270 v1(2518,1270) ; v1@2291.46,2099.54 ccw(c2282.93,2108.07) 2295,2108.07 ccw(c2307.07,2108.07) v1@2298.54,2099.54 ; v1(2295,2096) 2295,2358.66 2400.19,2463.85 2400.19,2656.2 2449.61,2705.62 CN2.28@2449.61,2706.79 ; 2416.1,2672.12 ccw(c2386.44,2701.78) CN2.28@2428.26,2705.09 ; 2416.93,2672.94 cw(c2447.05,2642.82) CN2.28@2448.75,2685.39 ; v1@2417,1341 ccw(c2404.93,1341) 2413.46,1349.54 ccw(c2422,1358.07) v1@2422,1346 ; CN2.28@2418.29,2704.3 cw(c2358.04,2699.52) 2400.78,2656.79 cw(c2445.82,2611.75) CN2.28@2448.35,2675.4 ; v1@2422,1336 cw(c2422,1323.93) 2430.54,1332.46 cw(c2439.07,1341) v1@2427,1341 ; v1@2451,1049 cw(c2451,1036.93) 2459.54,1045.46 cw(c2468.07,1054) v1@2456,1054 ; v1(2451,1054) 2465,1040 v1(2465,872) v1(2465,713.82) v1(2526.96,651.86) 2541,637.82 2541,528 2562,507 v1(2562,484) ; v1@2461.46,717.36 ccw(c2452.93,725.89) 2465,725.89 ccw(c2477.07,725.89) v1@2468.54,717.36 ; v1@2461.46,868.46 cw(c2452.93,859.93) 2465,859.93 cw(c2477.07,859.93) v1@2468.54,868.46 ; v1@2461.46,875.54 ccw(c2452.93,884.07) 2465,884.07 ccw(c2477.07,884.07) v1@2468.54,875.54 ; v1@2465,708.82 cw(c2465,696.75) 2473.54,705.29 cw(c2482.07,713.82) v1@2470,713.82 ; v1@2514.46,1266.46 ccw(c2505.93,1257.93) 2505.93,1270 ccw(c2505.93,1282.07) v1@2514.46,1273.54 ; v1@2521.96,651.86 ccw(c2509.89,651.86) 2518.43,660.4 ccw(c2526.96,668.93) v1@2526.96,656.86 ; v1@2526.96,646.86 cw(c2526.96,634.79) 2535.5,643.32 cw(c2544.03,651.86) v1@2531.96,651.86 ; v1@2558.46,487.54 ccw(c2549.93,496.07) 2562,496.07 ccw(c2574.07,496.07) v1@2565.54,487.54 ; v1@2858.46,694.46 cw(c2837.86,673.86) 2867,673.86 ; v1@2863.46,615.54 ccw(c2854.93,624.07) 2867,624.07 ccw(c2879.07,624.07) v1@2870.54,615.54 ; v1(2867,612) v1@2867,693
  Bottom Layer w20: U2.4@98.41,1278 cw(c75.15,1254.75) 108.04,1254.75 cw(c140.93,1254.75) U2.4@117.67,1278 ; U2.4@108.04,1287.63 v1(108.04,920) 108.04,898.96 275,732 275,260 P1.2@414,121 ; v1(198.61,1949.39) v1(342.39,1949.39) ; U2.2@272.61,1287.63 272.61,1300.22 U2.2@285.04,1300.22 ; U2.1@272.61,1627.79 531.21,1627.79 557.61,1601.39 v2(557.61,1503.79) v1(557.61,1455.79) ; U2.1@297.99,1618.16 cw(c321.24,1594.9) 321.24,1627.79 cw(c321.24,1660.67) U2.1@297.99,1637.42 ; P1.2@394.47,121 ccw(c347.33,121) 380.66,154.34 ccw(c414,187.67) P1.2@414,140.53 ; v1(496.61,1896) 540.61,1852 739,1852 v1(783,1808) 853.4,1808 945.58,1715.82 1013.82,1715.82 1057,1759 v1(1162,1759) 1162,1597 1121,1556 SWD.2@1073,1556 1172.21,1456.79 1172.21,1413.79 v1(1309,1277) 1171,1139 v1(1111,1139) ; 585,2480.51 ccw(c564.51,2480.51) v1(579,2495) 585,2489 v1(585,2350) 585,2211 v1(610,2186) 747,2186 860.61,2299.61 v2(860.61,2362.39) ; SWD.2@1073,1536.47 cw(c1073,1489.33) 1106.34,1522.66 cw(c1139.67,1556) SWD.2@1092.53,1556 ; SWD.2@1086.81,1542.19 cw(c1120.14,1508.86) 1120.14,1556 cw(c1120.14,1603.14) SWD.2@1086.81,1569.81 ; CN2.16@1849.61,2680.37 cw(c1849.61,2616.59) 1894.7,2661.69 cw(c1939.8,2706.79) 1876.02,2706.79 cw(c1939.8,2706.79) 1894.7,2751.89 cw(c1849.61,2796.98) CN2.16@1849.61,2733.21 ; v1(1892,99) 2321.82,99 CN1.27@2449.61,226.79 ; CN2.17@1923.19,2606.79 ccw(c1859.41,2606.79) 1904.51,2651.89 ccw(c1949.61,2696.98) CN2.17@1949.61,2633.21 ; CN2.17@1949.61,2606.79 CN2.16@1849.61,2706.79 1920.82,2778 2378.39,2778 CN2.28@2449.61,2706.79 2520.45,2777.63 2978.76,2777.63 CN2.40@3049.61,2706.79 ; v1(2295,2096) 2938,2096 v1(3151,2309) ; CN1.27@2423.19,226.79 cw(c2359.41,226.79) 2404.51,181.69 cw(c2449.61,136.59) 2449.61,200.37 cw(c2449.61,136.59) 2494.7,181.69 cw(c2539.8,226.79) CN1.27@2476.02,226.79 ; CN2.28@2423.19,2706.79 ccw(c2359.41,2706.79) 2404.51,2751.89 ccw(c2449.61,2796.98) 2449.61,2733.21 ccw(c2449.61,2796.98) 2494.7,2751.88 ccw(c2539.8,2706.79) CN2.28@2476.02,2706.79 ; CN1.27@2430.93,245.47 ccw(c2385.83,290.57) 2449.61,290.57 ccw(c2513.38,290.57) CN1.27@2468.29,245.47 ; CN1.28@2430.93,308.11 cw(c2385.83,263.01) 2449.61,263.01 cw(c2513.38,263.01) 2468.29,308.11 cw(c2513.38,263.01) 2513.38,326.79 cw(c2513.38,390.57) CN1.28@2468.29,345.47 ; CN1.30@2530.93,308.11 ccw(c2485.83,263.01) 2485.83,326.79 ccw(c2485.83,390.57) CN1.30@2530.93,345.47 ; CN1.30@2549.61,326.79 CN1.28@2449.61,326.79 CN1.27@2449.61,226.79 ; v1(2643.61,707.61) 2698.39,707.61 v1(2776,630) ; v1(2862,698) 2819,741 2771,741 2741.09,770.91 2741.09,822.97 2868.12,950 2927,950 3021,856 v1(3021,837) ccw(c2975.13,837) 3007.56,869.44 ; CN2.40@3023.19,2706.79 ccw(c2959.41,2706.79) 3004.51,2751.88 ccw(c3049.61,2796.98) CN2.40@3049.61,2733.21 ; v1(3168.31,1071.31) 3170.31,1069.31 v1(3170.31,835.31) ; v1(3192,2310) 3317,2310 3442,2435 3442,2614.39 CN2.46@3349.61,2706.79 ; CN2.46@3349.61,2680.37 cw(c3349.61,2616.59) 3394.7,2661.69 cw(c3439.8,2706.79) CN2.46@3376.02,2706.79 ; v1(3720,418) 3720,373 3433,86 2590.39,86 CN1.27@2449.61,226.79
  other v1: 1041,-43 1084,-39 3051,-14 2961,-10 3459,-5 3557,-4 912,4 1041,10 1083,14 3648,22 2850,44 2824,45 912,59 1041,67 874,86 3734,100 912,118 3479,135 879,195 3544.1,197.1 677,218 912,263 3742,265 677,279 878,316 912,320 3577,322 3579,377 912,381 1037,381 2549.61,390 1516,398 2964,399 3026,411 2549.61,414 3655,418 2937,419 3096.13,420 1517.73,428.21 3195.95,430 1824,437 3577,442 1038,450 1299.26,488 2359,510 1798.39,520 2357,557 2513,558 2258,559 2684,570 3375,575 610,581 3246,581 1379,582 1045,587 2937,608 3014,609 2687,616 1420,623 1045,630 2233,667 2180,670 3921,671 1045,678 545,686 1116,693 3077,701 1515,710 1269.3,734.3 3976,738 3879,756 1319.93,784.93 4053,812 3946,818 2388,871 2517,872 1426,885 4134,895 4019,896 3930,908 4080,955 3983,958 3170.31,967 3199,971 4157,994 4026,1004 2157,1031 3894,1032 4101,1041 3223,1046 2644,1053 3424,1063 2086,1068 1441,1069 2167,1069 3937,1092 3372,1116 3517,1116 1440,1134 4102,1136 1041,1139 2180,1146 2658,1146 2086,1150 3973,1153 3321,1168 4159,1178 1041,1183 1111,1183 3423,1183 852,1194 3386,1197 1443,1202 3056,1206 3352,1209 2758,1221 1813,1227 4102,1227 3915,1228 2660.49,1234 853,1248 3022,1251 3467,1262 1813,1263 3296,1296 1445,1298 494,1307 1276,1311 3986,1312 1218,1315 3274,1319 2897,1320 4103,1321 1832,1328 3469,1345 3895,1349 4159,1360 2897,1366 2959,1368 1443,1379 3250,1379 1662,1385.67 1832,1385.67 2006,1398 3948,1401 2561.28,1404.58 1291,1410 4102,1425 2227,1427 3882,1439 1832,1443.33 3903,1490 1832,1501 1172,1505 1288,1512 1663,1521 1205,1533 1743,1544 4100,1552 1765,1567 1245,1578 4158,1593 1291,1604 1819,1621 4102,1641 2483,1654 3383,1671 3009,1672 3065,1672 2757,1674 3304,1677 3514,1681 3380,1711 1869,1713 2757,1726 4102,1727 3100,1735 4160,1765 2182,1770 2798,1776 1642,1790 1817,1790 3423,1801 4102,1810 2836,1812 3103,1817 3402,1823 4102,1901 3087,1921 3369,1931 3429,1931 4158,1932 2106,1946 4102,1987 919,2033 3355,2053 3337,2077 4102,2077 873,2093 4160,2100 918,2104 3501,2110 3792,2136 1821,2144 1100,2163 3625,2167 4102,2170 917,2194 3432,2200 4158,2214 916,2237 4102,2253 3513,2264 1047,2269 3684,2281 4093,2312 1071,2313 1106,2313 469,2352 3465,2369 4112,2378 4016,2387 3597,2417 3948,2457 4031,2459 3498,2505 3861,2544 3938,2553 3785,2620 3707,2697 3784,2704 3656,2748 2150,2778 2346,2778 2637,2777.63 2179,2821 3580,2824 3678,2838 3195.95,2888 2297.52,2889 3295.78,2890 2597,2891 2796.65,2891 2896.47,2891 3423,2891 2397.34,2892 2497.17,2892 2696.82,2892 2996.3,2892 3096.13,2892 3474,2892
  other v2: 557.61,1410.79 595.61,1410.79 634.61,1410.79 595.61,1455.79 634.61,1455.79 595.61,1503.79 634.61,1503.79
LINK_LEDG: R33.1 U3.5 | length 985.6
  Top Layer w10: U3.5@586.76,1558.18 586.76,1606.46 669.61,1689.31 669.61,2405.31 655.61,2419.31 R33.1@618.61,2419.31 ; R33.1@627.45,2410.47 cw(c648.78,2389.13) 648.78,2419.31 cw(c648.78,2449.49) R33.1@627.45,2428.15
LINK_LEDR: R32.1 U3.6 | length 811.9
  Top Layer w10: U3.6@567.08,1558.18 567.08,1619.78 644.61,1697.31 644.61,2253.79 R32.1@618.61,2279.79 ; R32.1@618.61,2267.29 cw(c618.61,2237.11) 639.95,2258.45 cw(c661.28,2279.79) R32.1@631.11,2279.79
LINK_RESET: P1.5 R50.2 R54.1 SWD.5 | length 2671.8
  Top Layer w10: R50.2@695,900 728.98,900 756.98,872 756.98,794.02 v1(791,760) 1038,760 1073,795 SWD.5@1073,1256 1282,1465 R54.1@1377,1465 ; R50.2@703.84,891.16 cw(c725.18,869.82) 725.18,900 cw(c725.18,930.18) R50.2@703.84,908.84 ; v1@786,760 ccw(c773.93,760) 782.46,768.54 ccw(c791,777.07) v1@791,765 ; v1@794.54,756.46 cw(c803.07,747.93) 803.07,760 cw(c803.07,772.07) v1@794.54,763.54 ; SWD.5@1055.66,1238.66 cw(c1013.79,1196.79) 1073,1196.79 cw(c1132.21,1196.79) SWD.5@1090.34,1238.66 ; SWD.5@1062.73,1245.73 cw(c1037.93,1220.93) 1073,1220.93 cw(c1108.07,1220.93) SWD.5@1083.27,1245.73 ; SWD.5@1073,1270.53 ccw(c1073,1305.6) 1097.8,1280.8 ccw(c1122.6,1256) SWD.5@1087.53,1256 ; SWD.5@1073,1280.53 ccw(c1073,1339.74) 1114.87,1297.87 ccw(c1156.74,1256) SWD.5@1097.53,1256 ; R54.1@1368.16,1456.16 ccw(c1346.82,1434.82) 1346.82,1465 ccw(c1346.82,1495.18) R54.1@1368.16,1473.84
  Bottom Layer w10: P1.5@689.47,121 ccw(c630.26,121) 672.13,162.87 ccw(c714,204.74) P1.5@714,145.53 ; P1.5@699.47,121 ccw(c664.4,121) 689.2,145.8 ccw(c714,170.6) P1.5@714,135.53 ; P1.5@714,121 645,190 645,614 v1(791,760) ; v1@786,760 cw(c773.93,760) 782.46,751.46 cw(c791,742.93) v1@791,755
LINK_SWCLK: P1.4 R8.1 R51.2 | length 1636.9
  Top Layer w10: R51.2@694,985 717,985 ; R51.2@704.49,978.2 cw(c717,970.09) 717,985 ; R51.2@704.49,991.8 ccw(c717,999.91) 717,985 ; 727.98,985 717,985 ; R8.1@802.16,976.16 ccw(c780.82,954.82) 780.82,985 ccw(c780.82,1015.18) R8.1@802.16,993.84 ; R8.1@819.84,976.16 cw(c841.18,954.82) 841.18,985 cw(c841.18,1015.18) R8.1@819.84,993.84 ; v1@867.46,981.46 ccw(c858.93,972.93) 858.93,985 ccw(c858.93,997.07) v1@867.46,988.54 ; v1(871,985) R8.1@811,985 717,985
  Bottom Layer w10: P1.4@614,96.47 cw(c614,37.26) 655.87,79.13 cw(c697.74,121) P1.4@638.53,121 ; P1.4@614,106.47 cw(c614,71.4) 638.8,96.2 cw(c663.6,121) P1.4@628.53,121 ; P1.4@614,121 676,59 751,59 780,88 780,698 871,789 v1(871,985) ; v1@867.46,981.46 cw(c858.93,972.93) 871,972.93 cw(c883.07,972.93) v1@874.54,981.46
